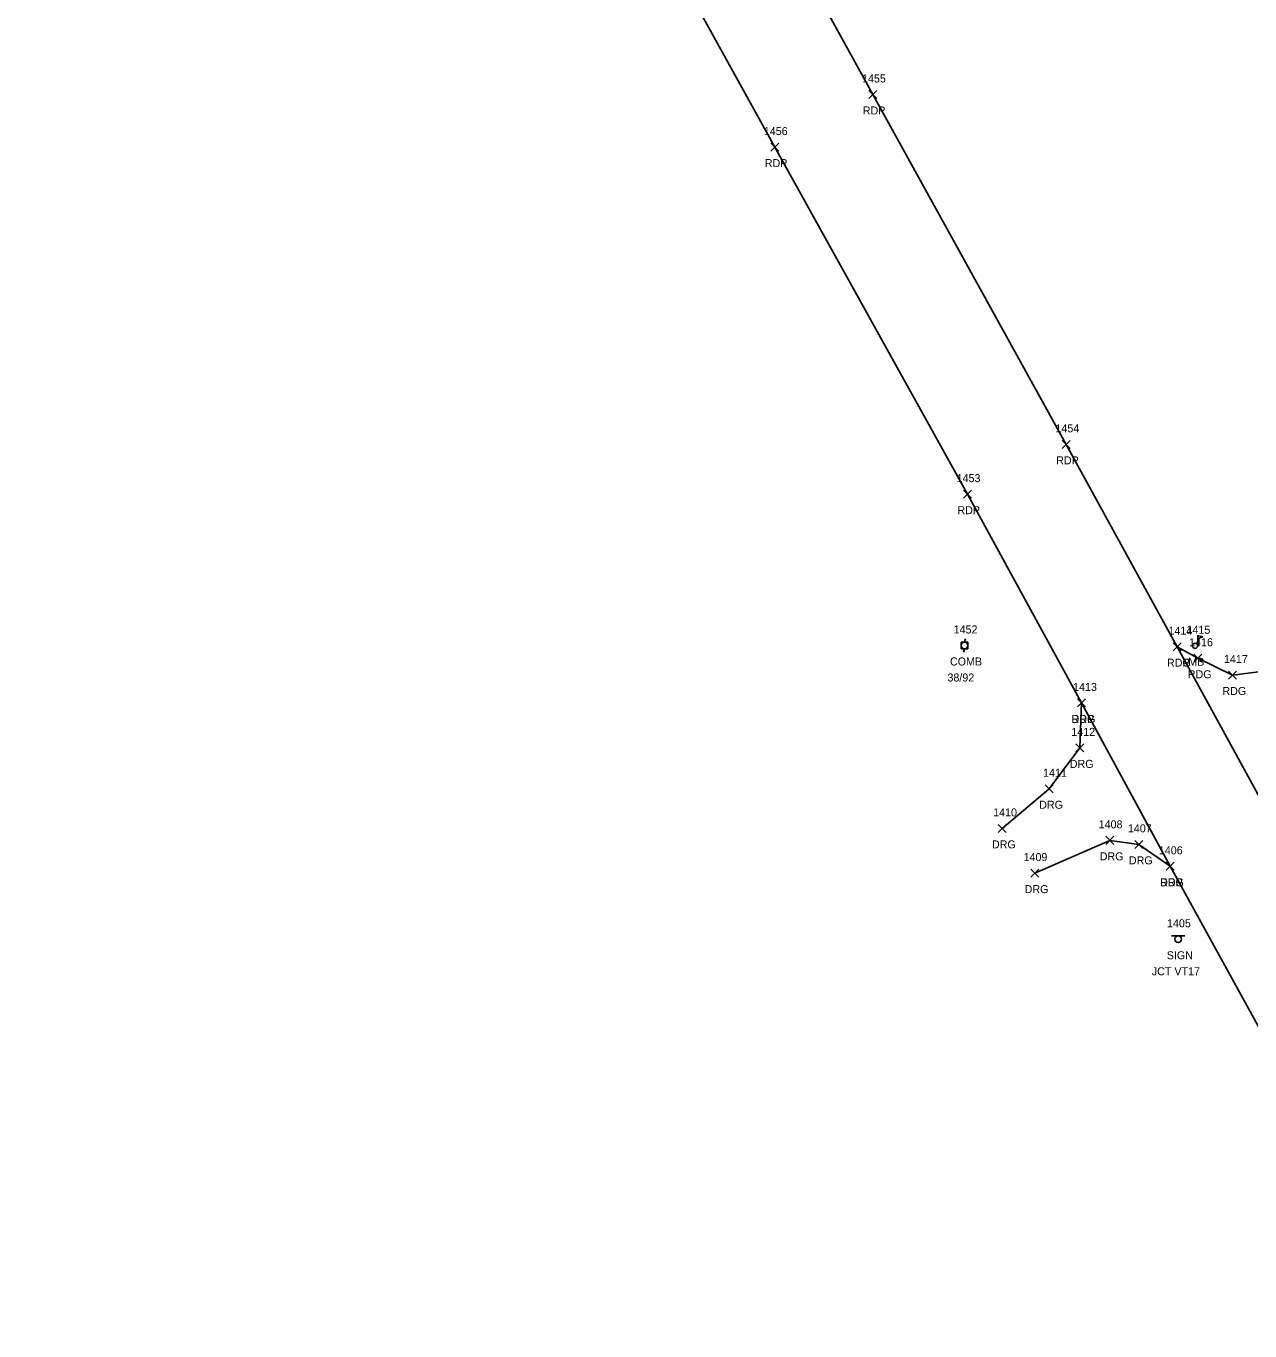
# Model space of a CAD drawing. Extents: x 1496556 to 1498241, y 599216 to 604470.
# Drawn here: x 1496572.3 to 1496878.1, y 603628.4 to 603954.5 of the extents above; entities that cross this region are included whole.
import ezdxf

# ---------------------------------------------------------------- set-up
doc = ezdxf.new("R2010")
doc.units = 0
for name, color, linetype in [('L_A', 7, 'Continuous'), ('L_I', 7, 'Continuous'), ('LMB', 7, 'Continuous'), ('P_A', 7, 'Continuous'), ('P_I', 7, 'Continuous'), ('P_TIC', 7, 'Continuous'), ('PET', 7, 'Continuous'), ('PEU', 7, 'Continuous'), ('R_A', 7, 'Continuous'), ('R_I', 7, 'Continuous'), ('R_TIC', 7, 'Continuous'), ('RDG', 7, 'Continuous'), ('S_A', 7, 'Continuous'), ('S_C', 7, 'Continuous'), ('S_I', 7, 'Continuous'), ('SSGN', 7, 'Continuous'), ('U_A', 7, 'Continuous'), ('U_C', 7, 'Continuous'), ('U_I', 7, 'Continuous'), ('UP', 7, 'Continuous')]:
    doc.layers.add(name, color=color, linetype=linetype)

msp = doc.modelspace()

# ---------------------------------------------------------------- linework, layer by layer
at = {"layer": 'LMB'}
for p, q in [((1496865, 603802.21), (1496866.3, 603801.83)), ((1496865.01, 603799.62), (1496865.01, 603802.21)), ((1496865.01, 603801.31), (1496866.29, 603801.82)), ((1496864.35, 603799.61), (1496864.35, 603799.61))]:
    msp.add_line(p, q, dxfattribs=at)
msp.add_circle((1496864.35, 603799.61), 0.656, dxfattribs=at)
at = {"layer": 'P_TIC'}
for points in [[(1496782.86, 603936.37), (1496784.86, 603938.37)], [(1496784.86, 603936.37), (1496782.86, 603938.37)], [(1496758.38, 603923.22), (1496760.38, 603925.22)], [(1496760.38, 603923.22), (1496758.38, 603925.22)], [(1496831.17, 603848.95), (1496833.17, 603850.95)], [(1496833.17, 603848.95), (1496831.17, 603850.95)], [(1496806.5, 603836.5), (1496808.5, 603838.5)], [(1496808.5, 603836.5), (1496806.5, 603838.5)], [(1496858.85, 603798.39), (1496860.85, 603800.39)], [(1496860.85, 603798.39), (1496858.85, 603800.39)], [(1496858.85, 603798.39), (1496860.85, 603800.39)], [(1496860.85, 603798.39), (1496858.85, 603800.39)], [(1496864.05, 603795.5), (1496866.05, 603797.5)], [(1496866.05, 603795.5), (1496864.05, 603797.5)], [(1496872.7, 603791.31), (1496874.7, 603793.31)], [(1496874.7, 603791.31), (1496872.7, 603793.31)], [(1496835.02, 603784.33), (1496837.02, 603786.33)], [(1496837.02, 603784.33), (1496835.02, 603786.33)], [(1496857.14, 603743.51), (1496859.14, 603745.51)], [(1496859.14, 603743.51), (1496857.14, 603745.51)]]:
    msp.add_lwpolyline(points, dxfattribs=at)
at = {"layer": 'PET'}
for points in [[(1497200.78, 603168.36), (1497190.31, 603189.95), (1497178.56, 603214.16), (1497156.38, 603259.17), (1497132.76, 603304.93), (1497107.74, 603351.81), (1497085.25, 603391.58), (1497052.51, 603451.39), (1497026.34, 603497.64), (1496978.11, 603585.44), (1496929.41, 603673.01), (1496891.52, 603741.51), (1496859.85, 603799.39), (1496832.17, 603849.95), (1496783.86, 603937.37), (1496736.46, 604023.53), (1496687.77, 604111.18), (1496657.13, 604166.72), (1496622.36, 604229.38), (1496597.22, 604275.47)], [(1497183.49, 603131.83), (1497176.45, 603149.42), (1497165.78, 603173.58), (1497153.07, 603202.24), (1497131.76, 603246.13), (1497108.09, 603291.8), (1497082.6, 603339.21), (1497060.69, 603378.6), (1497027.78, 603438.86), (1497002.63, 603483.06), (1496952.93, 603573.18), (1496904.09, 603661), (1496858.14, 603744.51), (1496836.02, 603785.33), (1496807.5, 603837.5), (1496759.38, 603924.22), (1496712.33, 604009.42), (1496662.89, 604098.73), (1496632.3, 604154.09), (1496599.03, 604214.45), (1496572.34, 604262.99)]]:
    msp.add_lwpolyline(points, dxfattribs=at)
at = {"layer": 'PEU'}
msp.add_lwpolyline([(1496859.85, 603799.39), (1496865.05, 603796.5), (1496873.7, 603792.31), (1496883.54, 603793.48), (1496900.05, 603803.04), (1496919.62, 603816.41), (1496939.61, 603828.85), (1496964, 603841.16), (1496990.45, 603851.4), (1497013.22, 603849.84), (1497044.46, 603840.34), (1497066.94, 603824.52), (1497091.56, 603803.58), (1497125.12, 603773.26), (1497155.15, 603746.18), (1497220.12, 603687.84), (1497248.27, 603664.84), (1497294.22, 603622.27), (1497317.74, 603605), (1497324.77, 603590.17), (1497316.71, 603584.14), (1497305.64, 603569), (1497293.3, 603576.17)], dxfattribs=at)
at = {"layer": 'R_TIC'}
for points in [[(1496835.02, 603784.33), (1496837.02, 603786.33)], [(1496837.02, 603784.33), (1496835.02, 603786.33)], [(1496834.57, 603773.1), (1496836.57, 603775.1)], [(1496836.57, 603773.1), (1496834.57, 603775.1)], [(1496826.94, 603762.89), (1496828.94, 603764.89)], [(1496828.94, 603762.89), (1496826.94, 603764.89)], [(1496815.13, 603752.99), (1496817.13, 603754.99)], [(1496817.13, 603752.99), (1496815.13, 603754.99)], [(1496842.06, 603750), (1496844.06, 603752)], [(1496844.06, 603750), (1496842.06, 603752)], [(1496849.34, 603749), (1496851.34, 603751)], [(1496851.34, 603749), (1496849.34, 603751)], [(1496857.14, 603743.51), (1496859.14, 603745.51)], [(1496859.14, 603743.51), (1496857.14, 603745.51)], [(1496823.29, 603741.81), (1496825.29, 603743.81)], [(1496825.29, 603741.81), (1496823.29, 603743.81)]]:
    msp.add_lwpolyline(points, dxfattribs=at)
at = {"layer": 'RDG'}
for points in [[(1496816.13, 603753.99), (1496827.94, 603763.89), (1496835.57, 603774.1), (1496836.02, 603785.33)], [(1496858.14, 603744.51), (1496850.34, 603750), (1496843.06, 603751), (1496824.29, 603742.81)]]:
    msp.add_lwpolyline(points, dxfattribs=at)
at = {"layer": 'SSGN'}
for p, q in [((1496858.49, 603727.13), (1496861.83, 603727.13)), ((1496860.14, 603726.3), (1496860.14, 603726.3))]:
    msp.add_line(p, q, dxfattribs=at)
msp.add_circle((1496860.14, 603726.3), 0.833, dxfattribs=at)
at = {"layer": 'UP'}
for p, q in [((1496805.91, 603798.86), (1496805.91, 603800.52)), ((1496805.91, 603800.52), (1496807.57, 603800.52)), ((1496806.99, 603801.36), (1496806.74, 603800.52)), ((1496807.57, 603800.52), (1496807.57, 603798.86)), ((1496807.57, 603798.86), (1496805.91, 603798.86)), ((1496806.49, 603798.02), (1496806.74, 603798.86)), ((1496806.74, 603799.69), (1496806.74, 603799.69))]:
    msp.add_line(p, q, dxfattribs=at)
msp.add_circle((1496806.74, 603799.69), 0.833, dxfattribs=at)

# ---------------------------------------------------------------- texts
at = {"layer": 'L_A'}
msp.add_text('MB', height=2, dxfattribs=at).set_placement((1496862.66, 603794.61))
at = {"layer": 'L_I'}
msp.add_text('1415', height=2, dxfattribs=at).set_placement((1496862.23, 603802.61))
at = {"layer": 'P_A'}
for s, p in [('RDP', (1496781.35, 603932.37)), ('RDP', (1496756.87, 603919.22)), ('RDP', (1496829.66, 603844.95)), ('RDP', (1496804.98, 603832.5)), ('RDG', (1496857.34, 603794.39)), ('RDP', (1496857.34, 603794.39)), ('RDG', (1496862.54, 603791.5)), ('RDG', (1496871.19, 603787.31)), ('RDP', (1496833.5, 603780.33)), ('RDP', (1496855.62, 603739.51))]:
    msp.add_text(s, height=2, dxfattribs=at).set_placement(p)
at = {"layer": 'P_I'}
for s, p in [('1455', (1496781.17, 603940.37)), ('1456', (1496756.63, 603927.22)), ('1454', (1496829.48, 603852.95)), ('1453', (1496804.8, 603840.5)), ('1414', (1496857.72, 603802.39)), ('1414', (1496857.72, 603802.39)), ('1416', (1496862.87, 603799.5)), ('1417', (1496871.57, 603795.31)), ('1413', (1496833.89, 603788.33)), ('1406', (1496855.31, 603747.51))]:
    msp.add_text(s, height=2, dxfattribs=at).set_placement(p)
at = {"layer": 'R_A'}
for p in [(1496833.5, 603780.33), (1496833.06, 603769.1), (1496825.42, 603758.89), (1496813.62, 603748.99), (1496840.54, 603746), (1496847.83, 603745), (1496855.62, 603739.51), (1496821.78, 603737.81)]:
    msp.add_text('DRG', height=2, dxfattribs=at).set_placement(p)
at = {"layer": 'R_I'}
for s, p in [('1413', (1496833.89, 603788.33)), ('1412', (1496833.45, 603777.1)), ('1411', (1496826.38, 603766.89)), ('1410', (1496813.92, 603756.99)), ('1408', (1496840.28, 603754)), ('1407', (1496847.57, 603753)), ('1409', (1496821.51, 603745.81)), ('1406', (1496855.31, 603747.51))]:
    msp.add_text(s, height=2, dxfattribs=at).set_placement(p)
at = {"layer": 'S_A'}
msp.add_text('SIGN', height=2, dxfattribs=at).set_placement((1496857.28, 603721.28))
at = {"layer": 'S_C'}
msp.add_text('JCT VT17', height=2, dxfattribs=at).set_placement((1496853.55, 603717.28))
at = {"layer": 'S_I'}
msp.add_text('1405', height=2, dxfattribs=at).set_placement((1496857.35, 603729.28))
at = {"layer": 'U_A'}
msp.add_text('COMB', height=2, dxfattribs=at).set_placement((1496803.13, 603794.69))
at = {"layer": 'U_C'}
msp.add_text('38/92', height=2, dxfattribs=at).set_placement((1496802.5, 603790.69))
at = {"layer": 'U_I'}
msp.add_text('1452', height=2, dxfattribs=at).set_placement((1496804.05, 603802.69))

doc.saveas('drawing.dxf')
